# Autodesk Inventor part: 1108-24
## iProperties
Created: 2007-03
Part Number: 1108-24
Document SubType Name: Modeling
Designer: Andy Moles
Material: Steel
Mass: 0.584827 g
Surface Area: 5.2094 cm^2
Volume: 0.0745003 cm^3
Density: 7.85 g/cm^3
Author: Andy Moles
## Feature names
1. Base1
